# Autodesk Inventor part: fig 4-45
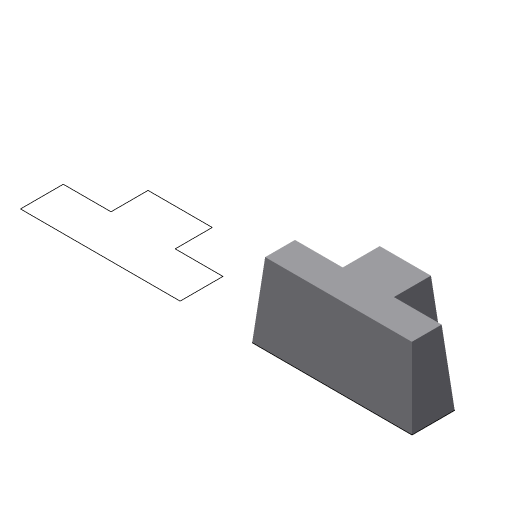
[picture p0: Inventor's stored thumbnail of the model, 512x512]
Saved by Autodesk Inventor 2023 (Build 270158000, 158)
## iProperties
Created: 2004-05
Part Number: fig 4-45
Document SubType Name: Modeling
Designer: CADCIM Technologies
Manufacturer: Standard
Standards Organization: Custom
Density: 1 g/cm^3
Material: Generic
Appearance: Default
Author: CADCIM Technologies
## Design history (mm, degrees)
sketch "Sketch1"
  geometry: L1 (31.783, 34.561)-(31.783, 22.933); L2 (31.783, 22.933)-(16.796, 22.933); L3 (16.796, 22.933)-(16.796, 9.496); L4 (16.796, 9.496)-(66.925, 9.496); L5 (66.925, 9.496)-(66.925, 22.933); L6 (66.925, 22.933)-(51.938, 22.933); L7 (51.938, 22.933)-(51.938, 34.561); L8 (51.938, 34.561)-(31.783, 34.561); L9 (-41.013, 34.561)-(-41.013, 22.933); L10 (-41.013, 22.933)-(-56, 22.933); L11 (-56, 22.933)-(-56, 9.496); L12 (-56, 9.496)-(-5.871, 9.496); L13 (-5.871, 9.496)-(-5.871, 22.933); L14 (-5.871, 22.933)-(-20.858, 22.933); L15 (-20.858, 22.933)-(-20.858, 34.561); L16 (-20.858, 34.561)-(-41.013, 34.561)
  constraints: 32 end point, 10 parallel, 4 equal length, 2 collinear, 2 perpendicular, 2 vertical
extrude "Extrusion1" new body sketch "Sketch1" distance "d0" = 23.25; taper "d1" = -5 deg
body "Solid1"
